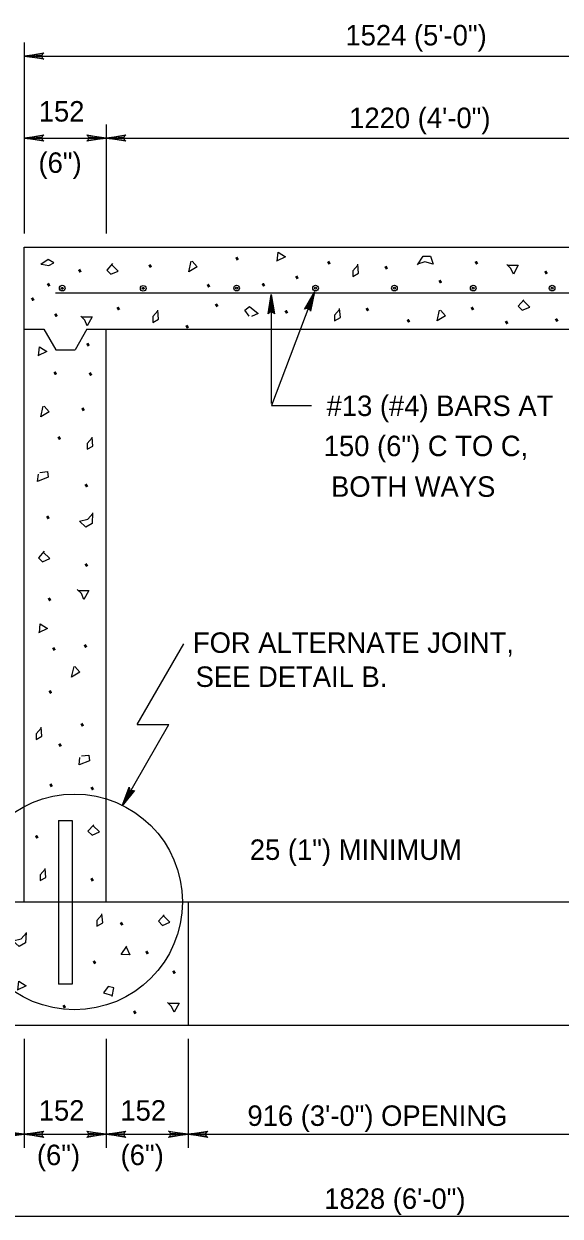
# Model space of a CAD drawing. Extents: x 638443 to 639347, y 298405 to 298999.
# Drawn here: x 638545.3 to 638623.8, y 298528.6 to 298703.3 of the extents above; entities that cross this region are included whole.
import ezdxf

# ---------------------------------------------------------------- set-up
doc = ezdxf.new("R2010")
doc.units = 0
doc.layers.add('2', color=7, linetype='Continuous')
doc.layers.add('3', color=7, linetype='Continuous')

msp = doc.modelspace()

# ---------------------------------------------------------------- linework, layer by layer
at = {"layer": '2'}
for p, q in [((638545.34, 298700.58), (638545.34, 298672.58)), ((638545.34, 298698.58), (638665.34, 298698.58)), ((638557.34, 298688.58), (638557.34, 298672.58)), ((638545.34, 298686.58), (638557.34, 298686.58)), ((638557.34, 298686.58), (638653.34, 298686.58)), ((638545.34, 298574.58), (638545.34, 298670.58)), ((638545.34, 298670.58), (638665.34, 298670.58)), ((638549.9, 298663.89), (638661.38, 298663.89)), ((638587.86, 298664.04), (638581.56, 298647.39)), ((638581.52, 298663.66), (638581.52, 298647.66)), ((638545.34, 298658.58), (638548.18, 298658.58)), ((638554.5, 298658.58), (638557.34, 298658.58)), ((638557.34, 298574.58), (638557.34, 298658.58)), ((638557.34, 298658.58), (638653.34, 298658.58)), ((638549.97, 298655.53), (638552.81, 298655.53)), ((638581.56, 298647.39), (638587.44, 298647.39)), ((638561.89, 298600.62), (638568.73, 298612.46)), ((638559.66, 298588.73), (638566.53, 298600.62)), ((638561.89, 298600.62), (638566.53, 298600.62)), ((638550.34, 298586.58), (638552.34, 298586.58)), ((638550.34, 298586.58), (638550.34, 298562.58)), ((638552.34, 298586.58), (638552.34, 298562.58)), ((638677.34, 298574.58), (638533.34, 298574.58)), ((638569.34, 298574.58), (638569.34, 298556.58)), ((638552.34, 298562.58), (638550.34, 298562.58)), ((638533.34, 298556.58), (638677.34, 298556.58)), ((638545.34, 298554.58), (638545.34, 298538.58)), ((638557.34, 298554.58), (638557.34, 298538.58)), ((638569.34, 298554.58), (638569.34, 298538.58)), ((638533.34, 298540.58), (638545.34, 298540.58)), ((638545.34, 298540.58), (638557.34, 298540.58)), ((638557.34, 298540.58), (638569.34, 298540.58)), ((638569.34, 298540.58), (638641.34, 298540.58)), ((638533.34, 298528.58), (638677.34, 298528.58))]:
    msp.add_line(p, q, dxfattribs=at)
for points in [[(638548.07, 298698.24), (638547.96, 298698.44), (638545.34, 298698.58), (638548.07, 298698.24), (638548.21, 298698.12), (638545.34, 298698.58), (638547.96, 298698.71), (638548.06, 298698.91), (638545.34, 298698.58), (638548.21, 298699.04), (638548.06, 298698.91)], [(638548.07, 298686.24), (638547.96, 298686.44), (638545.34, 298686.58), (638548.07, 298686.24), (638548.21, 298686.12), (638545.34, 298686.58), (638547.96, 298686.71), (638548.06, 298686.91), (638545.34, 298686.58), (638548.21, 298687.04), (638548.06, 298686.91)], [(638554.62, 298686.93), (638554.72, 298686.73), (638557.34, 298686.58), (638554.62, 298686.93), (638554.48, 298687.05), (638557.34, 298686.58), (638554.72, 298686.45), (638554.63, 298686.26), (638557.34, 298686.58), (638554.48, 298686.13), (638554.63, 298686.26)], [(638560.07, 298686.24), (638559.96, 298686.44), (638557.34, 298686.58), (638560.07, 298686.24), (638560.21, 298686.12), (638557.34, 298686.58), (638559.96, 298686.71), (638560.06, 298686.91), (638557.34, 298686.58), (638560.21, 298687.04), (638560.06, 298686.91)], [(638542.62, 298540.93), (638542.72, 298540.73), (638545.34, 298540.58), (638542.62, 298540.93), (638542.48, 298541.05), (638545.34, 298540.58), (638542.72, 298540.45), (638542.63, 298540.26), (638545.34, 298540.58), (638542.48, 298540.13), (638542.63, 298540.26)], [(638548.07, 298540.24), (638547.96, 298540.44), (638545.34, 298540.58), (638548.07, 298540.24), (638548.21, 298540.12), (638545.34, 298540.58), (638547.96, 298540.71), (638548.06, 298540.91), (638545.34, 298540.58), (638548.21, 298541.04), (638548.06, 298540.91)], [(638554.62, 298540.93), (638554.72, 298540.73), (638557.34, 298540.58), (638554.62, 298540.93), (638554.48, 298541.05), (638557.34, 298540.58), (638554.72, 298540.45), (638554.63, 298540.26), (638557.34, 298540.58), (638554.48, 298540.13), (638554.63, 298540.26)], [(638560.07, 298540.24), (638559.96, 298540.44), (638557.34, 298540.58), (638560.07, 298540.24), (638560.21, 298540.12), (638557.34, 298540.58), (638559.96, 298540.71), (638560.06, 298540.91), (638557.34, 298540.58), (638560.21, 298541.04), (638560.06, 298540.91)], [(638566.62, 298540.93), (638566.72, 298540.73), (638569.34, 298540.58), (638566.62, 298540.93), (638566.48, 298541.05), (638569.34, 298540.58), (638566.72, 298540.45), (638566.63, 298540.26), (638569.34, 298540.58), (638566.48, 298540.13), (638566.63, 298540.26)], [(638572.07, 298540.24), (638571.96, 298540.44), (638569.34, 298540.58), (638572.07, 298540.24), (638572.21, 298540.12), (638569.34, 298540.58), (638571.96, 298540.71), (638572.06, 298540.91), (638569.34, 298540.58), (638572.21, 298541.04), (638572.06, 298540.91)]]:
    msp.add_lwpolyline(points, dxfattribs=at)
at = {"layer": '3'}
for p, q in [((638550.93, 298664.58), (638550.93, 298664.58)), ((638562.79, 298664.55), (638562.79, 298664.55)), ((638576.45, 298664.58), (638576.45, 298664.58)), ((638588.01, 298664.58), (638588.01, 298664.58)), ((638599.56, 298664.58), (638599.56, 298664.58)), ((638611.12, 298664.58), (638611.12, 298664.58)), ((638622.67, 298664.58), (638622.67, 298664.58)), ((638548.18, 298658.58), (638549.97, 298655.53)), ((638554.5, 298658.58), (638552.81, 298655.53))]:
    msp.add_line(p, q, dxfattribs=at)
for points in [[(638582.41, 298668.54), (638582.54, 298669.86), (638583.61, 298669.15), (638582.3, 298668.54)], [(638602.94, 298667.97), (638603.78, 298669.28), (638604.85, 298669.28), (638605.23, 298668.08), (638604.02, 298668.43), (638602.94, 298668.08)], [(638547.87, 298668.09), (638548.95, 298667.88), (638549.68, 298668.29), (638548.84, 298668.78), (638547.76, 298668.02)], [(638558.27, 298668.17), (638557.42, 298667.22), (638558.03, 298666.61), (638559.11, 298667.09), (638558.14, 298668.06)], [(638569.94, 298668.54), (638570.66, 298667.71), (638569.46, 298666.98), (638569.81, 298668.54)], [(638594.19, 298667.95), (638593.46, 298667.11), (638593.46, 298666.28), (638594.3, 298666.76), (638594.19, 298668.08)], [(638616.15, 298667.95), (638617.71, 298667.95), (638616.99, 298666.63), (638616.61, 298667.47), (638616.02, 298668.06)], [(638586.58, 298661.61), (638586.8, 298661.64), (638587.86, 298664.04), (638586.58, 298661.61), (638586.41, 298661.52), (638587.86, 298664.04), (638587.05, 298661.54), (638587.2, 298661.38), (638587.86, 298664.04), (638587.27, 298661.2), (638587.2, 298661.38)], [(638581.18, 298660.94), (638581.38, 298661.04), (638581.52, 298663.66), (638581.18, 298660.94), (638581.06, 298660.8), (638581.52, 298663.66), (638581.65, 298661.04), (638581.84, 298660.94), (638581.52, 298663.66), (638581.98, 298660.8), (638581.84, 298660.94)], [(638618.54, 298662.88), (638617.69, 298661.94), (638618.3, 298661.33), (638619.38, 298661.81), (638618.41, 298662.77)], [(638553.73, 298660.38), (638555.28, 298660.38), (638554.56, 298659.06), (638554.19, 298659.9), (638553.6, 298660.49)], [(638564.89, 298661.23), (638564.17, 298660.4), (638564.17, 298659.56), (638565.01, 298660.05), (638564.89, 298661.36)], [(638578.29, 298660.47), (638577.64, 298661.37), (638578.31, 298661.88), (638579.62, 298660.84), (638578.61, 298660.4)], [(638591.53, 298661.47), (638590.81, 298660.64), (638590.81, 298659.8), (638591.65, 298660.29), (638591.53, 298661.6)], [(638606.3, 298661.34), (638607.03, 298660.51), (638605.82, 298659.79), (638606.17, 298661.34)], [(638547.42, 298654.68), (638547.55, 298656), (638548.63, 298655.3), (638547.31, 298654.68)], [(638548.25, 298647.26), (638548.98, 298646.43), (638547.77, 298645.71), (638548.12, 298647.26)], [(638555.29, 298642.62), (638554.56, 298641.79), (638554.56, 298640.96), (638555.4, 298641.44), (638555.29, 298642.75)], [(638547.62, 298637.58), (638548.72, 298637.69), (638548.83, 298636.86), (638547.27, 298636.24), (638547.4, 298637.34)], [(638555.34, 298631.66), (638555.28, 298630.11), (638554.34, 298629.57), (638553.42, 298630.43), (638554.64, 298630.72), (638555.4, 298631.57)], [(638548.25, 298626.02), (638547.4, 298625.08), (638548.01, 298624.46), (638549.09, 298624.95), (638548.12, 298625.91)], [(638553.24, 298620.29), (638554.8, 298620.29), (638554.08, 298618.97), (638553.71, 298619.81), (638553.11, 298620.4)], [(638547.55, 298614.08), (638547.68, 298615.39), (638548.75, 298614.69), (638547.44, 298614.08)], [(638552.76, 298609.12), (638553.49, 298608.29), (638552.28, 298607.56), (638552.63, 298609.12)], [(638547.81, 298600.11), (638547.08, 298599.27), (638547.08, 298598.44), (638547.92, 298598.92), (638547.81, 298600.24)], [(638553.71, 298596.04), (638554.8, 298596.15), (638554.91, 298595.32), (638553.36, 298594.71), (638553.49, 298595.8)], [(638561.32, 298590.92), (638561.1, 298590.93), (638559.66, 298588.73), (638561.32, 298590.92), (638561.5, 298590.98), (638559.66, 298588.73), (638560.86, 298591.07), (638560.74, 298591.25), (638559.66, 298588.73), (638560.7, 298591.44), (638560.74, 298591.25)], [(638555.53, 298585.95), (638554.67, 298585.01), (638555.29, 298584.4), (638556.36, 298584.88), (638555.4, 298585.84)], [(638548.4, 298579.42), (638547.68, 298578.58), (638547.68, 298577.75), (638548.51, 298578.23), (638548.4, 298579.55)], [(638556.71, 298572.76), (638555.99, 298571.93), (638555.99, 298571.09), (638556.83, 298571.57), (638556.71, 298572.89)], [(638565.84, 298572.74), (638564.99, 298571.8), (638565.6, 298571.19), (638566.68, 298571.67), (638565.71, 298572.63)], [(638545.6, 298570.17), (638545.54, 298568.62), (638544.61, 298568.08), (638543.68, 298568.94), (638544.9, 298569.23), (638545.66, 298570.08)], [(638560.25, 298568.07), (638560.79, 298566.86), (638559.51, 298566.94), (638560.35, 298568.13)], [(638544.4, 298561.7), (638544.53, 298563.02), (638545.61, 298562.32), (638544.29, 298561.7)], [(638558.21, 298560.77), (638558.48, 298562.02), (638557.64, 298562.24), (638556.95, 298561.29), (638558.27, 298560.93)], [(638566.45, 298559.78), (638568.01, 298559.78), (638567.29, 298558.46), (638566.92, 298559.29), (638566.32, 298559.89)]]:
    msp.add_lwpolyline(points, dxfattribs=at)
for centre, radius in [((638550.9, 298664.58), 0.419), ((638550.9, 298664.55), 0.146), ((638562.76, 298664.55), 0.419), ((638562.76, 298664.55), 0.146), ((638576.45, 298664.58), 0.419), ((638576.45, 298664.58), 0.146), ((638588.01, 298664.58), 0.419), ((638588.01, 298664.58), 0.146), ((638599.56, 298664.58), 0.419), ((638599.56, 298664.58), 0.146), ((638611.12, 298664.58), 0.419), ((638611.12, 298664.58), 0.146), ((638622.67, 298664.58), 0.419), ((638622.67, 298664.58), 0.146), ((638552.7, 298574.63), 15.81)]:
    msp.add_circle(centre, radius, dxfattribs=at)

# ---------------------------------------------------------------- texts
for s, p in [('1524 (5\'-0")', (638592.39, 298700.15)), ('152', (638547.46, 298688.99)), ('1220 (4\'-0")', (638592.94, 298688.03)), ('(6")', (638547.42, 298681.47)), ('#13 (#4) BARS AT', (638589.63, 298645.84)), ('150 (6") C TO C,', (638589.21, 298639.96)), ('BOTH WAYS', (638590.28, 298634)), ('FOR ALTERNATE JOINT,', (638570.04, 298611.13)), ('SEE DETAIL B.', (638570.44, 298606.14)), ('25 (1") MINIMUM', (638578.38, 298580.79)), ('152', (638547.46, 298542.58)), ('152', (638559.42, 298542.58)), ('916 (3\'-0") OPENING', (638578.03, 298541.81)), ('(6")', (638547.19, 298536.06)), ('(6")', (638559.45, 298536.06)), ('1828 (6\'-0")', (638589.28, 298529.65))]:
    msp.add_text(s, height=3, dxfattribs=at).set_placement(p)
for p in [(638576.88, 298669.39), (638553.84, 298667.6), (638564.15, 298668.3), (638590.33, 298668.78), (638598.73, 298668.06), (638611.94, 298668.78), (638585.65, 298666.63), (638606.65, 298666.02), (638622.14, 298667.35), (638549.27, 298665.55), (638572.69, 298665.42), (638580.74, 298665.55), (638546.94, 298663.44), (638573.89, 298662.55), (638550.35, 298661.1), (638559.48, 298662.07), (638584.1, 298661.58), (638595.97, 298661.94), (638611.35, 298662.07), (638569.57, 298659.41), (638601.98, 298660.27), (638616.37, 298660.03), (638623.7, 298660.38), (638555.04, 298656.78), (638550.24, 298652.59), (638555.4, 298652.46), (638554.32, 298647.3), (638550.83, 298643.09), (638554.8, 298636.13), (638549.16, 298631.46), (638554.8, 298624.48), (638549.4, 298619.45), (638550.05, 298612.18), (638554.67, 298612.61), (638549.52, 298605.88), (638554.19, 298601.07), (638550.94, 298598.1), (638549.63, 298592.2), (638555.67, 298591.74), (638547.53, 298584.65), (638555.64, 298578.38), (638559.96, 298571.91), (638555.99, 298566.27), (638563.69, 298567.7), (638567.64, 298564.82), (638551.56, 298559.78), (638561.89, 298558.94)]:
    msp.add_text('.', height=3, rotation=210, dxfattribs=at).set_placement(p)

doc.saveas('drawing.dxf')
